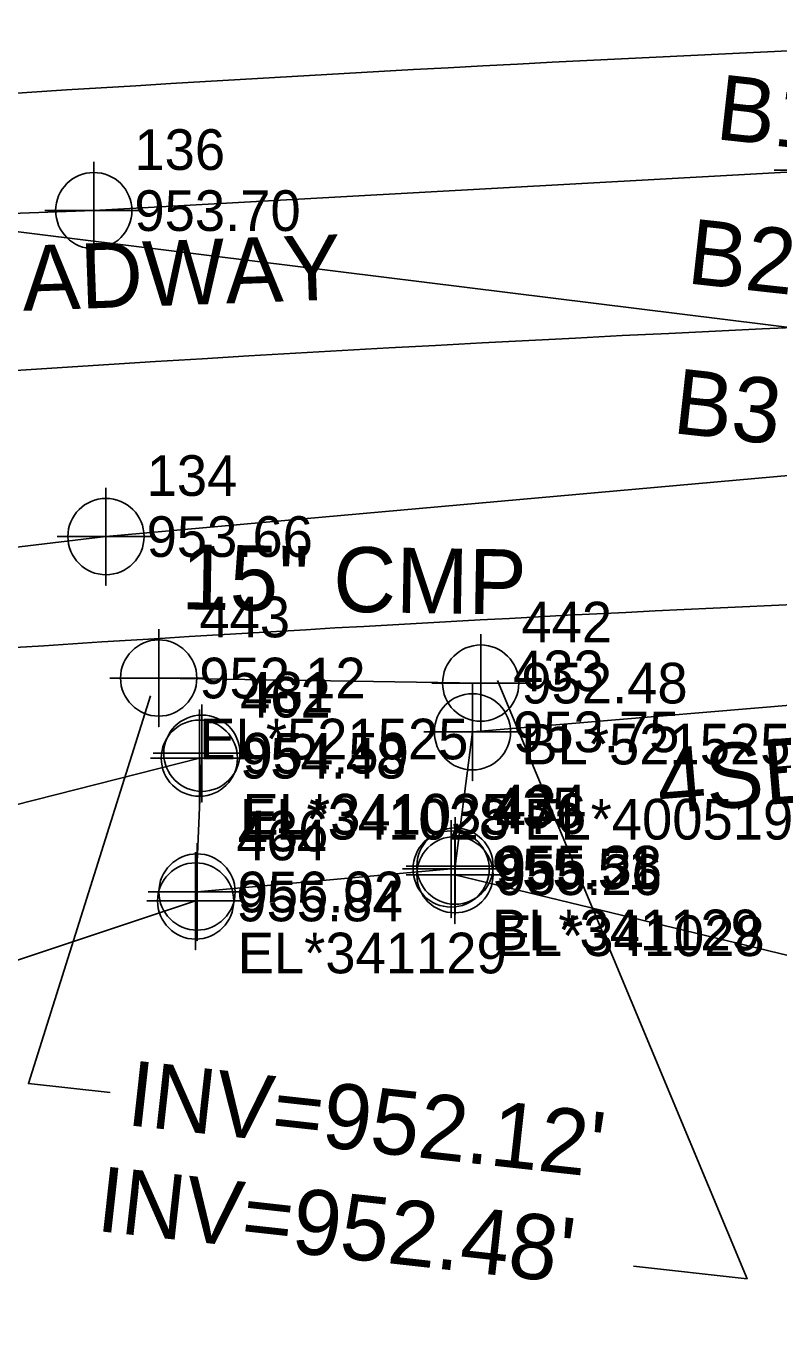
# Model space of a CAD drawing. Extents: x 1150279 to 1151282, y 654632 to 657999.
# Drawn here: x 1150667.5 to 1150713.8, y 657071.3 to 657151.4 of the extents above; entities that cross this region are included whole.
import ezdxf

# ---------------------------------------------------------------- set-up
doc = ezdxf.new("R2010")
doc.units = 0
for name, color, linetype in [('COGO Default Chain', 7, 'Continuous'), ('COGO Default Curve', 7, 'Continuous'), ('Exist Horizontal Alignment', 7, 'Continuous'), ('Exist Other Culture Fence Line', 7, 'Continuous'), ('Exist Other Culture Fence Line Cogo Comment', 7, 'Continuous'), ('Exist Other Culture Fence Line Cogo Elevation', 7, 'Continuous'), ('Exist Other Culture Fence Line Cogo Number', 7, 'Continuous'), ('Exist Other Culture Fence Line Cogo Point CELL', 7, 'Continuous'), ('Exist Other Culture Fence Line Text', 7, 'Continuous'), ('Exist Other Culture Gate', 7, 'Continuous'), ('Exist Other Culture Gate Cogo Comment', 7, 'Continuous'), ('Exist Other Culture Gate Cogo Elevation', 7, 'Continuous'), ('Exist Other Culture Gate Cogo Number', 7, 'Continuous'), ('Exist Other Culture Gate Cogo Point CELL', 7, 'Continuous'), ('Exist Other Culture Located Object Text', 7, 'Continuous'), ('Exist Right of Way Line', 7, 'Continuous'), ('Exist Roads EOP', 7, 'Continuous'), ('Exist Roads EOP Cogo Elevation', 7, 'Continuous'), ('Exist Roads EOP Cogo Number', 7, 'Continuous'), ('Exist Roads EOP Cogo Point CELL', 7, 'Continuous'), ('Exist Roads EOP Text', 7, 'Continuous'), ('Exist Structure Minor Pipes CMP 15 Inch', 7, 'Continuous'), ('Exist Structure Minor Pipes CMP 15 Inch Cogo Comment', 7, 'Continuous'), ('Exist Structure Minor Pipes CMP 15 Inch Cogo Elevation', 7, 'Continuous'), ('Exist Structure Minor Pipes CMP 15 Inch Cogo Number', 7, 'Continuous'), ('Exist Structure Minor Pipes CMP 15 Inch Cogo Point CELL', 7, 'Continuous'), ('Exist Structure Minor Pipes CMP 15 Inch Leader', 7, 'Continuous'), ('Exist Structure Minor Pipes CMP 15 Inch Text', 7, 'Continuous')]:
    doc.layers.add(name, color=color, linetype=linetype)

msp = doc.modelspace()

# ---------------------------------------------------------------- linework, layer by layer
at = {"layer": 'COGO Default Chain'}
msp.add_line((1150614.756, 657145.261), (1150931.292, 657106.062), dxfattribs=at)
msp.add_arc((1150828.329, 654635.498), 2500, 91.662542, 95.877614, dxfattribs=at)
at = {"layer": 'COGO Default Curve'}
msp.add_arc((1150828.329, 654635.498), 2500, 91.662542, 95.877614, dxfattribs=at)
at = {"layer": 'Exist Horizontal Alignment'}
msp.add_arc((1150828.329, 654635.498), 2500, 91.662542, 95.877614, dxfattribs=at)
at = {"layer": 'Exist Other Culture Fence Line'}
for points in [[(1150742.984, 657123.479), (1150720.806, 657110.237), (1150694.904, 657108.056), (1150693.831, 657099.804)], [(1150604.364, 657025.637), (1150606.718, 657040.787), (1150614.664, 657070.42), (1150624.719, 657081.252), (1150654.476, 657089.879), (1150677.88, 657097.661), (1150678.264, 657106.743)], [(1150601.904, 657018.952), (1150605.153, 657042.825), (1150611.977, 657072.418), (1150621.899, 657082.995), (1150637.683, 657096.184), (1150678.109, 657106.438)], [(1150771.144, 656993.524), (1150752.14, 657032.017), (1150729.275, 657075.13), (1150719.487, 657093.066), (1150693.827, 657099.275)]]:
    msp.add_lwpolyline(points, dxfattribs=at)
at = {"layer": 'Exist Other Culture Fence Line Cogo Point CELL'}
for points in [[(1150694.904, 657111.056), (1150694.904, 657105.056), (1150694.904, 657108.056), (1150697.904, 657108.056), (1150691.904, 657108.056)], [(1150678.109, 657109.438), (1150678.109, 657103.438), (1150678.109, 657106.438), (1150681.109, 657106.438), (1150675.109, 657106.438)], [(1150678.264, 657109.743), (1150678.264, 657103.743), (1150678.264, 657106.743), (1150681.264, 657106.743), (1150675.264, 657106.743)], [(1150693.831, 657102.804), (1150693.831, 657096.804), (1150693.831, 657099.804), (1150696.831, 657099.804), (1150690.831, 657099.804)], [(1150693.827, 657102.275), (1150693.827, 657096.275), (1150693.827, 657099.275), (1150696.827, 657099.275), (1150690.827, 657099.275)], [(1150677.88, 657100.661), (1150677.88, 657094.661), (1150677.88, 657097.661), (1150680.88, 657097.661), (1150674.88, 657097.661)]]:
    msp.add_lwpolyline(points, dxfattribs=at)
for centre in [(1150694.904, 657108.056), (1150678.264, 657106.743), (1150678.109, 657106.438), (1150693.831, 657099.804), (1150693.827, 657099.275), (1150677.88, 657097.661)]:
    msp.add_circle(centre, 2.344, dxfattribs=at)
at = {"layer": 'Exist Other Culture Gate'}
msp.add_line((1150693.593, 657099.63), (1150677.966, 657098.213), dxfattribs=at)
at = {"layer": 'Exist Other Culture Gate Cogo Point CELL'}
for points in [[(1150693.593, 657102.63), (1150693.593, 657096.63), (1150693.593, 657099.63), (1150696.593, 657099.63), (1150690.593, 657099.63)], [(1150677.966, 657101.213), (1150677.966, 657095.213), (1150677.966, 657098.213), (1150680.966, 657098.213), (1150674.966, 657098.213)]]:
    msp.add_lwpolyline(points, dxfattribs=at)
for centre in [(1150693.593, 657099.63), (1150677.966, 657098.213)]:
    msp.add_circle(centre, 2.344, dxfattribs=at)
at = {"layer": 'Exist Right of Way Line'}
for radius, end in [(2517, 94.774746), (2483, 94.310193)]:
    msp.add_arc((1150828.329, 654635.498), radius, 91.662542, end, dxfattribs=at)
at = {"layer": 'Exist Roads EOP'}
for points in [[(1150716.457, 657142.572), (1150671.616, 657140.096), (1150622.503, 657138.316)], [(1150717.083, 657124.055), (1150672.367, 657120.059), (1150646.285, 657116.941)]]:
    msp.add_lwpolyline(points, dxfattribs=at)
at = {"layer": 'Exist Roads EOP Cogo Point CELL'}
for points in [[(1150716.457, 657145.572), (1150716.457, 657139.572), (1150716.457, 657142.572), (1150719.457, 657142.572), (1150713.457, 657142.572)], [(1150671.616, 657143.096), (1150671.616, 657137.096), (1150671.616, 657140.096), (1150674.616, 657140.096), (1150668.616, 657140.096)], [(1150672.367, 657123.059), (1150672.367, 657117.059), (1150672.367, 657120.059), (1150675.367, 657120.059), (1150669.367, 657120.059)]]:
    msp.add_lwpolyline(points, dxfattribs=at)
for centre in [(1150671.616, 657140.096), (1150672.367, 657120.059)]:
    msp.add_circle(centre, 2.344, dxfattribs=at)
at = {"layer": 'Exist Structure Minor Pipes CMP 15 Inch'}
msp.add_line((1150695.411, 657111.053), (1150675.608, 657111.366), dxfattribs=at)
at = {"layer": 'Exist Structure Minor Pipes CMP 15 Inch Cogo Point CELL'}
for points in [[(1150675.608, 657114.366), (1150675.608, 657108.366), (1150675.608, 657111.366), (1150678.608, 657111.366), (1150672.608, 657111.366)], [(1150695.411, 657114.053), (1150695.411, 657108.053), (1150695.411, 657111.053), (1150698.411, 657111.053), (1150692.411, 657111.053)]]:
    msp.add_lwpolyline(points, dxfattribs=at)
for centre in [(1150675.608, 657111.366), (1150695.411, 657111.053)]:
    msp.add_circle(centre, 2.344, dxfattribs=at)
at = {"layer": 'Exist Structure Minor Pipes CMP 15 Inch Leader'}
for points in [[(1150696.437, 657111.217), (1150711.797, 657074.444), (1150704.813, 657075.217)], [(1150675.107, 657110.278), (1150667.593, 657086.435), (1150672.616, 657085.879)]]:
    msp.add_lwpolyline(points, dxfattribs=at)

# ---------------------------------------------------------------- texts
at = {"layer": 'Exist Other Culture Fence Line Cogo Comment'}
for s, p in [('EL*341035', (1150680.764, 657101.743)), ('EL*341028 EL*400519', (1150680.609, 657101.438)), ('EL*341028', (1150696.327, 657094.275))]:
    msp.add_text(s, height=2.5, dxfattribs=at).set_placement(p)
at = {"layer": 'Exist Other Culture Fence Line Cogo Elevation'}
for s, p in [('953.75', (1150697.404, 657106.807)), ('954.48', (1150680.609, 657105.188)), ('954.59', (1150680.764, 657105.493)), ('955.38', (1150696.331, 657098.554)), ('955.26', (1150696.327, 657098.025)), ('955.84', (1150680.38, 657096.411))]:
    msp.add_text(s, height=2.5, dxfattribs=at).set_placement(p)
at = {"layer": 'Exist Other Culture Fence Line Cogo Number'}
for s, p in [('433', (1150697.404, 657110.557)), ('462', (1150680.609, 657108.938)), ('481', (1150680.764, 657109.243)), ('476', (1150696.327, 657101.775)), ('434', (1150696.331, 657102.304)), ('464', (1150680.38, 657100.161))]:
    msp.add_text(s, height=2.5, dxfattribs=at).set_placement(p)
at = {"layer": 'Exist Other Culture Fence Line Text'}
msp.add_text('4SBW', height=4, rotation=4.81184, dxfattribs=at).set_placement((1150706.414, 657103.004))
at = {"layer": 'Exist Other Culture Gate Cogo Comment'}
for s, p in [('BL*341129', (1150696.093, 657094.63)), ('EL*341129', (1150680.466, 657093.213))]:
    msp.add_text(s, height=2.5, dxfattribs=at).set_placement(p)
at = {"layer": 'Exist Other Culture Gate Cogo Elevation'}
for s, p in [('955.51', (1150696.093, 657098.38)), ('956.02', (1150680.466, 657096.963))]:
    msp.add_text(s, height=2.5, dxfattribs=at).set_placement(p)
at = {"layer": 'Exist Other Culture Gate Cogo Number'}
for s, p in [('435', (1150696.093, 657102.13)), ('436', (1150680.466, 657100.713))]:
    msp.add_text(s, height=2.5, dxfattribs=at).set_placement(p)
at = {"layer": 'Exist Other Culture Located Object Text'}
for s, p in [('B1', (1150709.784, 657144.499)), ('B2', (1150708.024, 657135.634)), ('B3', (1150707.148, 657126.428))]:
    msp.add_text(s, height=4, rotation=353.6867, dxfattribs=at).set_placement(p)
at = {"layer": 'Exist Roads EOP Cogo Elevation'}
for s, p in [('953.70', (1150674.116, 657138.846)), ('953.66', (1150674.867, 657118.809))]:
    msp.add_text(s, height=2.5, dxfattribs=at).set_placement(p)
at = {"layer": 'Exist Roads EOP Cogo Number'}
for s, p in [('136', (1150674.116, 657142.596)), ('134', (1150674.867, 657122.559))]:
    msp.add_text(s, height=2.5, dxfattribs=at).set_placement(p)
at = {"layer": 'Exist Roads EOP Text'}
msp.add_text("20' +/- PAVED ROADWAY", height=4, rotation=2.07519, dxfattribs=at).set_placement((1150623.329, 657132.342))
at = {"layer": 'Exist Structure Minor Pipes CMP 15 Inch Cogo Comment'}
for s, p in [('EL*521525', (1150678.108, 657106.366)), ('BL*521525', (1150697.911, 657106.053))]:
    msp.add_text(s, height=2.5, dxfattribs=at).set_placement(p)
at = {"layer": 'Exist Structure Minor Pipes CMP 15 Inch Cogo Elevation'}
for s, p in [('952.12', (1150678.108, 657110.116)), ('952.48', (1150697.911, 657109.803))]:
    msp.add_text(s, height=2.5, dxfattribs=at).set_placement(p)
at = {"layer": 'Exist Structure Minor Pipes CMP 15 Inch Cogo Number'}
for s, p in [('443', (1150678.108, 657113.866)), ('442', (1150697.911, 657113.553))]:
    msp.add_text(s, height=2.5, dxfattribs=at).set_placement(p)
at = {"layer": 'Exist Structure Minor Pipes CMP 15 Inch Text'}
for s, rotation, p in [('15" CMP', 359.09532, (1150676.981, 657115.591)), ("INV=952.12'", 353.6867, (1150673.566, 657083.892)), ("INV=952.48'", 353.6867, (1150671.706, 657077.389))]:
    msp.add_text(s, height=4, rotation=rotation, dxfattribs=at).set_placement(p)

doc.saveas('drawing.dxf')
